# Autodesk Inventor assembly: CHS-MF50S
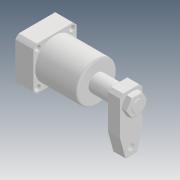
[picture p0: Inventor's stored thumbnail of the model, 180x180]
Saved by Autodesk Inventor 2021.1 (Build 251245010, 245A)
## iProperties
Created: 2019-04
Part Number: CHS-MF50S
Description: STEP AP203
Document SubType Name: Assembly
Designer: user
Title: chs-mf50s_asm.STEP
Revision Number: ÈÎºÎ
Sending System: SolidWorks 2017
Preprocessor: SwSTEP 2.0
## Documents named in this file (11)
- D:\Vault_2016\Projekty\Clamptek\Hydraulic\CHS\CHS-50\Inventor\CHS-MF50S\CHS-MF50S.iam
- D:\Vault_2016\Projekty\Clamptek\Hydraulic\CHS\CHS-50\Inventor\CHS-MF50S\CHS-MF50BT.ipt
- D:\Vault_2016\Projekty\Clamptek\Hydraulic\CHS\CHS-50\Inventor\CHS-MF50S\CHS-50SHSG_4.ipt
- D:\Vault_2016\Projekty\Clamptek\Hydraulic\CHS\CHS-50\Inventor\CHS-MF50S\M6_1.ipt
- D:\Vault_2016\Projekty\Clamptek\Hydraulic\CHS\CHS-50\Inventor\CHS-MF50S\PRT0002.ipt
- D:\Vault_2016\Projekty\Clamptek\Hydraulic\CHS\CHS-50\Inventor\CHS-MF50S\M6LM.ipt
- D:\Vault_2016\Projekty\Clamptek\Hydraulic\CHS\CHS-50\Inventor\CHS-MF50S\PRT0003.ipt
- D:\Vault_2016\Projekty\Clamptek\Hydraulic\CHS\CHS-50\Inventor\CHS-MF50S\PRT0001.ipt
- D:\Vault_2016\Projekty\Clamptek\Hydraulic\CHS\CHS-50\Inventor\CHS-MF50S\PRT0006.ipt
- D:\Vault_2016\Projekty\Clamptek\Hydraulic\CHS\CHS-50\Inventor\CHS-MF50S\CHS-50SYB_4.ipt
- D:\Vault_2016\Projekty\Clamptek\Hydraulic\CHS\CHS-50\Inventor\CHS-MF50S\M20LM_4.ipt
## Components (11 placed, 11 different names)
1. CHS-MF50BT_1
2. CHS-50SHSG_4_2
3. M6_1_3
4. M6_1_4
5. PRT0002_5
6. M6LM_6
7. PRT0003_7
8. PRT0001_8
9. PRT0006_9
10. CHS-50SYB_4_10
11. M20LM_4_11
